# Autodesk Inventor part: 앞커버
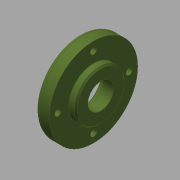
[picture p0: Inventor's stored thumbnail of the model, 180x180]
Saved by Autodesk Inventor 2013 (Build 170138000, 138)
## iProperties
Created: 2015-12
Part Number: 앞커버
Document SubType Name: Modeling
Designer: mdu
Density: 2.71 g/cm^3
Material: 알루미늄 6061
Mass: 70.9323 g
Surface Area: 93.9278 cm^2
Volume: 26.1743 cm^3
Author: mdu
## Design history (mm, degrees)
sketch "스케치1"
  geometry: L1 (-7.5, 0)-(7.5, 0); L2 (-7.5, 0)-(-7.5, 31); L3 (-7.5, 31)-(2.5, 31); L4 (2.5, 31)-(2.5, 17.5); L5 (2.5, 17.5)-(7.5, 17.5); L6 (7.5, 17.5)-(7.5, 0); 2 further points
  constraints: 12 end point, 3 perpendicular, 1 coincident, 1 horizontal, 1 midpoint, 1 parallel
  dimensions: "d0" = 15 distance of L1.start L1.end; "d1" = 62 diameter of L3 L1; "d2" = 35 diameter of L5 L1; "d5" = 10 distance of L2.end L3.end
revolve "회전1" sketch "스케치1" stored, may be unused: angle "d6" = 90 deg
sketch "스케치2" dims "d42" = 50
  geometry: 3 further points
  constraints: 2 vertical alignment, 1 coincident, 2 other
hole "구멍1" sketch "스케치2" at (0, 25) diameter "d8" = 4.5; stored, may be unused: countersink angle "d12" = 90 deg, drill point angle "d14" = 118 deg; dims "d9" = 6, "d10" = 8, "d11" = 4.4, "d13" = 8
hole "구멍2" diameter "d20" = 18; stored, may be unused: countersink angle "d24" = 90 deg, drill point angle "d26" = 0 deg; dims "d18" = 10, "d19" = 10, "d21" = 6, "d22" = 8, "d23" = 4.4, "d25" = 8
hole "구멍3" diameter "d34" = 30; stored, may be unused: countersink angle "d38" = 90 deg, drill point angle "d40" = 0 deg; dims "d32" = 10, "d33" = 10, "d35" = 6, "d36" = 4, "d37" = 2, "d39" = 7.3
fillet "모깎기1" dims "d27" = 3, "d41" = 0.3
chamfer "모따기1" distance "d29" = 1; stored, may be unused: second distance "d30" = 2, angle "d31" = 45 deg
node "솔리드1"
pattern_circular "원형 패턴1" dims angle "d16" = 360 deg
